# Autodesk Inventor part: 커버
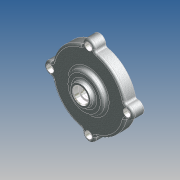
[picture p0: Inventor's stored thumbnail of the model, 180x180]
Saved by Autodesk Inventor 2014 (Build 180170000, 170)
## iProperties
Created: 2012-05
Part Number: 커버
Document SubType Name: 모델링
Designer: SeoGD™
Material: 알루미늄 6061
Appearance: 알루미늄 캐스트
Mass: 196.657 g
Surface Area: 278.607 cm^2
Volume: 72.5671 cm^3
Density: 2.71 g/cm^3
변환 표준: STEP AP214IS
파일 이름: C:\Users\SeoGD\Desktop\?쒗뿕\而ㅻ쾭-1.stp
전처리기: Build: 253, Release: 2010 SP1 - Date: Wed 07/29/2009
전송 단위: 밀리미터
불확실성: 0.01
Author: SeoGD™
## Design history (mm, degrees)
sketch "스케치1"
  geometry: L1 (0, 0)-(0, 26); L2 (50, 0)-(50, 15); L3 (50, 15)-(25, 15); L4 (25, 15)-(25, 21); L5 (25, 21)-(15, 21); L6 (15, 21)-(13.66, 26); L7 (13.66, 26)-(10, 26); L8 (50, 0)-(45, 0); L9 (45, 0)-(45, 10); L10 (45, 10)-(14.5, 10); L11 (14.5, 10)-(13.266, 3); L12 (13.266, 3)-(11, 3); L13 (11, 3)-(11, 16); L14 (11, 16)-(7.5, 16); L15 (7.5, 16)-(7.5, 19); L16 (7.5, 19)-(10, 19); L17 (10, 19)-(10, 26)
  constraints: 34 end point, 10 parallel, 2 perpendicular, 2 point on line, 1 vertical
  dimensions: "d11" = 100 diameter of L2 L1; "d12" = 22 diameter of L13 L1; "d13" = 90 diameter of L9 L1; "d14" = 15 distance between parallel lines of L3 L8; "d15" = 10 distance between parallel lines of L8 L10; "d16" = 29 diameter of L10.end L1; "d17" = 100 deg angle of L11 L10; "d18" = 7 distance between parallel lines of L12 L10; "d19" = 13 distance between parallel lines of L14 L12; "d20" = 3 distance between parallel lines of L16 L14; "d21" = 15 diameter of L15 L1; "d22" = 20 diameter of L17 L1; "d23" = 30 diameter of L5.end L1; "d24" = 6 distance between parallel lines of L5 L3; "d25" = 50 diameter of L4 L1; "d26" = 105 deg angle of L5 L6; "d50" = 26 distance of L1.start L1.end
revolve "회전1" sketch "스케치1" stored, may be unused: angle "d27" = 90 deg
sketch "스케치2" dims "d29" = 104
  geometry: A1 r 8.5 centre (0, 52) between (8.074, 49.344) and (-8.074, 49.344); A2 r 50 centre (0, 0) between (-8.074, 49.344) and (8.074, 49.344) reference; 2 further points
  constraints: 4 point on circle, 2 vertical alignment, 1 centre point, 1 coincident, 2 other
  dimensions: "d28" = 17 diameter of A1
extrude "돌출1" join sketch "스케치2" stored distance "d30" = 10; taper "d31" = 0 deg
fillet "모깎기3" dims "d32" = 3
fillet "모깎기4" dims "d45" = 3, "d46" = 0.2
chamfer "모따기1" distance "d47" = 1; stored, may be unused: second distance "d48" = 2, angle "d49" = 45 deg
hole "구멍2" diameter "d38" = 5.5; stored, may be unused: countersink angle "d42" = 90 deg, drill point angle "d44" = 118 deg; dims "d36" = 10, "d37" = 10, "d39" = 6, "d40" = 9.5, "d41" = 5.4, "d43" = 8
node "솔리드1"
node "솔리드 본체"
node "곡면 본체"
pattern_circular "원형 패턴1" dims angle "d34" = 360 deg
pattern_circular "원형 패턴2" dims angle "d52" = 360 deg
node "솔리드2"
